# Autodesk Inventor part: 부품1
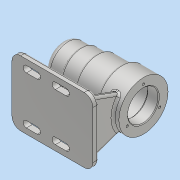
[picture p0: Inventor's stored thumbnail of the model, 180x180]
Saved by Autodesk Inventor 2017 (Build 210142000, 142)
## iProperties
Part Number: 부품1
Material: 알루미늄 6061
Document SubType Name: Modeling
Designer: MRC
Density: 2.7 g/cm^3
Appearance: 알루미늄 - 평지
Mass: 690.248 g
Surface Area: 701.718 cm^2
Volume: 255.647 cm^3
Author: MRC
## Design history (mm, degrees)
sketch "스케치1"
  geometry: L1 (0, 0)-(-112, 0); L2 (0, 0)-(0, 34); L3 (0, 34)-(-32, 34); L4 (-32, 34)-(-32, 30); L5 (-32, 30)-(-66, 30); L6 (-66, 30)-(-66, 27); L7 (-66, 27)-(-88, 27); L8 (-88, 27)-(-88, 25); L9 (-88, 25)-(-112, 25); L10 (-112, 25)-(-112, 0); L11 (-99, 17.5)-(-91.331, 17.5); L12 (-91.331, 17.5)-(-91.331, 17.5); L13 (-91.331, 17.5)-(-81, 17.5); L14 (-81, 17.5)-(-81, 21); L15 (-81, 21)-(-69, 21); L16 (-69, 21)-(-69, 24); L17 (-69, 24)-(-15, 24); L18 (-15, 24)-(-15, 21); L19 (-15, 21)-(0, 21); L20 (-99, 17.5)-(-99, 16); L21 (-99, 16)-(-103, 16); L22 (-103, 16)-(-103, 10.5); L23 (-103, 10.5)-(-106, 10.5); L24 (-106, 10.5)-(-106, 0)
  constraints: 48 end point, 17 perpendicular, 5 point on line, 3 vertical, 1 horizontal
  dimensions: "d0" = 112 distance of L1.start L1.end; "d1" = 68 diameter of L3 L1; "d2" = 60 diameter of L5 L1; "d3" = 54 diameter of L7 L1; "d4" = 50 diameter of L9 L1; "d5" = 24 distance from line of L7.end L10; "d6" = 46 distance from line of L6.end L10; "d7" = 80 distance from line of L3.end L10; "d8" = 42 diameter of L19 L1; "d9" = 48 diameter of L17 L1; "d10" = 35 diameter of L13 L1; "d11" = 32 diameter of L20.end L1; "d12" = 21 diameter of L23 L1; "d13" = 18 distance between parallel lines of L20 L14; "d14" = 12 distance between parallel lines of L16 L14; "d15" = 54 distance from line of L18 L16.end; "d16" = 15 distance between parallel lines of L2 L18; "d17" = 3 distance of L22.end L23.end; "d18" = 4 distance of L20.end L21.end
revolve "회전1" stored, may be unused: angle "d19" = 90 deg
fillet "모깎기1" dims "d20" = 0.3
fillet "모깎기2" dims "d21" = 3
chamfer "모따기1" distance "d22" = 1; stored, may be unused: second distance "d23" = 2, angle "d24" = 45 deg
fillet "모깎기3" dims "d25" = 8
node "작업 평면1"
sketch "스케치2"
  geometry: L1 (112, 45)-(0, 45); L2 (0, 45)-(0, -45); L3 (0, -45)-(112, -45); L4 (112, -45)-(112, 45); L5 (112, 45)-(0, -45); L6 (0, 45)-(112, -45); L7 (0, 34)-(0, -34) reference; 3 further points
  constraints: 12 end point, 4 midpoint, 2 parallel, 1 horizontal, 1 perpendicular
  dimensions: "d27" = 112 distance of L3.end L2.end; "d28" = 90 distance of L2.end L1.end
extrude "돌출1" join sketch "스케치2" distance "d29" = 8; taper "d30" = 0 deg
fillet "모깎기4" dims "d31" = 12
sketch "스케치3"
  geometry: L1 (-112, -33)-(-112, 33) reference; L2 (-77, 33)-(-92, 33); L3 (-77, 37.5)-(-92, 37.5); L4 (-92, 28.5)-(-77, 28.5); L5 (-52, 28.5)-(-37, 28.5); L6 (-37, 33)-(-52, 33); L7 (-37, 37.5)-(-52, 37.5); A1 r 4.5 centre (-77, 33) between (-77, 28.5) and (-77, 37.5); A2 r 4.5 centre (-92, 33) between (-92, 37.5) and (-92, 28.5); A3 r 4.5 centre (-37, 33) between (-37, 28.5) and (-37, 37.5); A4 r 4.5 centre (-52, 33) between (-52, 37.5) and (-52, 28.5); 3 further points
  constraints: 16 end point, 8 point on circle, 8 tangent, 4 centre point, 2 horizontal, 2 midpoint, 2 parallel, 1 horizontal alignment
  dimensions: "d32" = 33 distance from line of point (0, 0) L2; "d33" = 9 distance between parallel lines of L3 L4; "d34" = 15 distance of L3.start L3.end; "d35" = 20 distance from line of L3.end L1; "d38" = 9 distance between parallel lines of L7 L5; "d39" = 15 distance of L7.start L7.end; "d40" = 25 distance of L7.end L3.start
extrude "돌출2" cut sketch "스케치3" distance "d36" = 8; taper "d37" = 0 deg
extrude "돌출3" cut sketch "스케치3" distance "d41" = 8; taper "d42" = 0 deg
node "작업 평면2"
fillet "모깎기5" dims "d45" = 3
node "작업 평면3"
sketch "스케치5"
  geometry: L1 (9.591, 45.342)-(-4, 8); L2 (56.409, 45.342)-(70, 8); L3 (-4.5, 8)-(4.5, 8) reference; L4 (66, 8)-(0, 8) reference; L5 (78, 0)-(78, 8) reference; L6 (-12, 8)-(-12, 0) reference; L7 (-4, 8)-(70, 8); L8 (-4.5, 8)-(4.5, 8) reference; A1 r 34 centre (33, 70) between (9.591, 45.342) and (56.409, 45.342) reference; 1 further point
  constraints: 6 end point, 2 point on circle, 2 point on line, 1 collinear
  dimensions: "d47" = 8 distance from line of L2.end L5; "d48" = 8 distance from line of L1.end L6; "d49" = 110 deg angle of L3 L1; "d50" = 110 deg angle of L4 L2
extrude "돌출4" join sketch "스케치5" distance "d51" = 8; taper "d52" = 0 deg
sketch "스케치6"
  geometry: L1 (-80.101, -43.716)-(-85, -62); L2 (-100, -62)-(-12, -62) reference; L3 (-8, -24.658)-(-8, -62) reference; 1 further point
  constraints: 2 end point, 1 point on line
  dimensions: "d53" = 105 deg angle of L1 L2; "d54" = 77 distance from line of L3 L1.end
feature "리브1" sketch "스케치6" dims "d55" = 1, "d56" = 8, "d57" = 0, "d58" = 0, "d59" = 1, "d60" = 1
fillet "모깎기6" dims "d61" = 3
fillet "모깎기7" dims "d62" = 3
fillet "모깎기8" dims "d63" = 3
sketch "스케치7"
  geometry: C1 r 22 at (0, 0) reference; 1 further point
  constraints: 1 horizontal alignment
  dimensions: "d64" = 26 distance of point (-26, 0) C1.centre
hole "구멍1" sketch "스케치7" at (-26, 0) diameter "d65" = 3.242; stored, may be unused: countersink angle "d69" = 90 deg, drill point angle "d71" = 118 deg; dims "d66" = 8, "d67" = 4, "d68" = 2, "d70" = 11
sketch "스케치8"
  geometry: L1 (-112, 33)-(-112, -33) reference; 2 further points
  constraints: 1 horizontal alignment, 1 other
  dimensions: "d75" = 12 distance from line of point (-100, 0) L1
feature "엠보싱1" sketch "스케치8" dims "d0" = 112, "d1" = 68, "d2" = 60, "d3" = 54, "d4" = 50, "d5" = 24, "d6" = 46, "d7" = 80, "d8" = 42, "d9" = 48, "d10" = 35, "d11" = 32, "d12" = 21, "d13" = 18, "d14" = 12, "d15" = 54, "d16" = 15, "d17" = 3, "d18" = 4, "d76" = 0.5, "d77" = 0
fillet "모깎기9" dims "d78" = 0.3
node "솔리드1"
mirror "미러1"
pattern_circular "원형 패턴1" dims angle "d73" = 360 deg
other parameters: "d46" = -8
